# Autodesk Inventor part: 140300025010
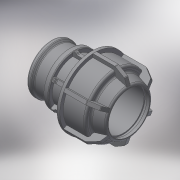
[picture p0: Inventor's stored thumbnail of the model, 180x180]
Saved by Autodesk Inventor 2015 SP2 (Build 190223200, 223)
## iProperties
Created: 2017-08
Part Number: 140300025010
Material: Generic
Description: PLASSON L.14 FEMALE ADAPTOR (SILVER) 25-1"
Document SubType Name: Modeling
Designer: KIM
Density: 1 g/cm^3
Appearance: Default
Author: KIM
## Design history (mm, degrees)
derived "140300.ipt"
feature "Solid1::140300.ipt"
tag "TaggingFeature1"
body "Solid1"
other parameters: "d1" = 25, "d2" = 54, "d4" = 15 deg, "d5" = 35.64, "d6" = 11.7612, "d9" = 30.291, "d11" = 39.3783, "d12" = 36.3492, "d13" = 42.4074, "d14" = 21, "d16" = 25.5, "d17" = 2.7, "d19" = 6.3, "d20" = 135 deg, "d21" = 6.3, "d22" = 36.3492, "d23" = 22.5, "d24" = 2.7, "d25" = 45, "d26" = 37.5, "d27" = 2.7, "d28" = 135 deg, "d29" = 1.62, "d31" = 1.25, "d44" = 0.5, "d45" = 0.75, "d46" = 150 deg, "d49" = 2.5, "d50" = 0, "d51" = 0.5, "d52" = 1, "d53" = 45 deg, "d55" = 7.284, "d56" = 2.5, "d57" = 0, "d58" = 0.75, "d61" = 360 deg, "d_" = 25, "G_" = 30.291, "l_" = 54, "l_2" = 21, "d54" = 18.21
